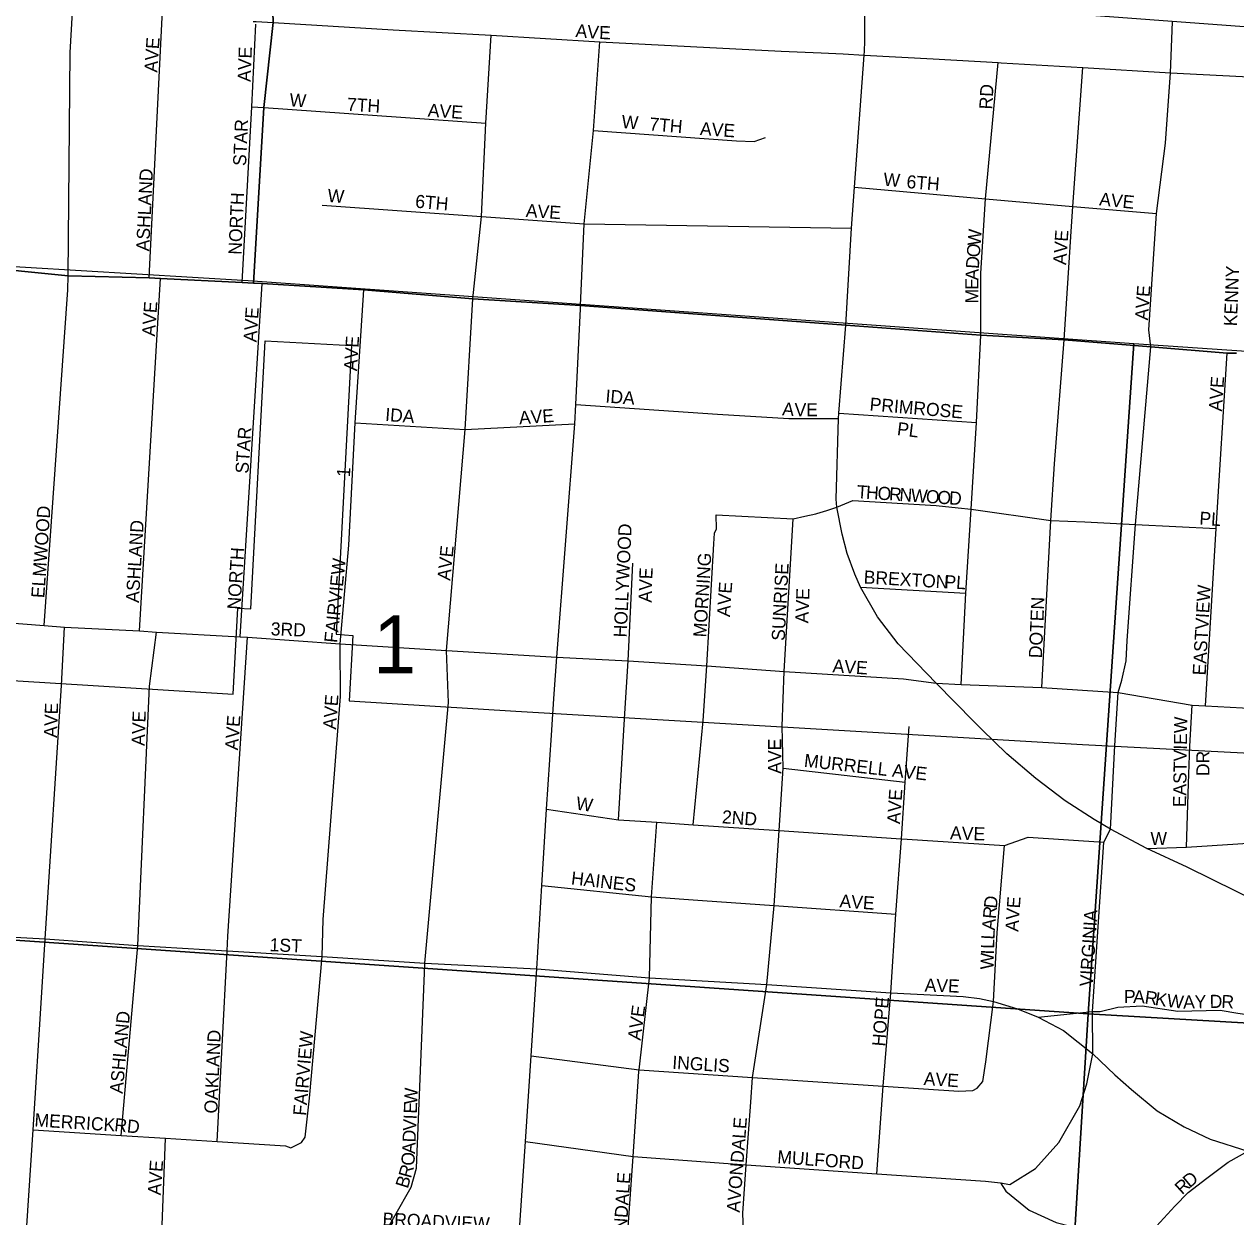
# Model space of a CAD drawing. Extents: x 0 to 34, y -6.2 to 22.
# Drawn here: x 3.949 to 4.825, y 19.243 to 20.105 of the extents above; entities that cross this region are included whole.
import ezdxf

# ---------------------------------------------------------------- set-up
doc = ezdxf.new("R2010")
doc.units = 0
for name, color, linetype in [('GM_X_City_Street', 7, 'Continuous'), ('GM_X_City_Street_Text', 7, 'Continuous'), ('GM_X_Corporation', 7, 'Continuous'), ('GM_X_Section', 7, 'Continuous'), ('GM_X_Section_Text', 7, 'Continuous'), ('GM_X_Township', 7, 'Continuous')]:
    doc.layers.add(name, color=color, linetype=linetype)

msp = doc.modelspace()

# ---------------------------------------------------------------- linework, layer by layer
at = {"layer": 'GM_X_City_Street'}
for points in [[(4.55628, 20.08526), (4.55664, 20.09249), (4.55647, 20.10992), (4.55433, 20.12701), (4.55105, 20.14132), (4.54402, 20.15913), (4.53474, 20.17767), (4.52852, 20.18768), (4.52129, 20.19705), (4.51422, 20.20462), (4.50912, 20.20987), (4.50344, 20.21461), (4.49515, 20.22105), (4.4677, 20.2393), (4.324, 20.3266), (4.19675, 20.40486), (4.17844, 20.41553), (4.15875, 20.42298), (4.14634, 20.42702)], [(3.96346, 19.67023), (3.98059, 19.91279), (3.98086, 19.92294), (3.98244, 20.08445), (3.98408, 20.11355), (3.98655, 20.13903), (3.98852, 20.15761)], [(4.03954, 19.92149), (4.04886, 20.10993), (4.05083, 20.14511)], [(4.10661, 19.91804), (4.11352, 20.04512), (4.11655, 20.10492)], [(4.11465, 20.10685), (4.11664, 20.10677), (4.12905, 20.10601), (4.21566, 20.1007), (4.28652, 20.09692), (4.3651, 20.09199), (4.49614, 20.08542), (4.52499, 20.08415)], [(4.73722, 19.58334), (4.73968, 19.62181), (4.7422, 19.63051), (4.74531, 19.64456), (4.74615, 19.65938), (4.75199, 19.74324), (4.76318, 19.87149), (4.76179, 19.88392), (4.76731, 19.96792), (4.77381, 20.01883), (4.77743, 20.06963), (4.77874, 20.10662)], [(4.25581, 19.61458), (4.25436, 19.65214), (4.26765, 19.81193), (4.27333, 19.90633), (4.27952, 19.9658), (4.28257, 20.03329), (4.28652, 20.09692)], [(4.35108, 19.89896), (4.3512, 19.90135), (4.35383, 19.96053), (4.3605, 20.02804), (4.3651, 20.09199)], [(4.52499, 20.08415), (4.54086, 20.08345), (4.55614, 20.08246), (4.60579, 20.07966), (4.65281, 20.07703), (4.65509, 20.07689)], [(4.54291, 19.88718), (4.54694, 19.95735), (4.54908, 19.98695), (4.55614, 20.08246), (4.55628, 20.08526)], [(4.62625, 19.62756), (4.62953, 19.69349), (4.63348, 19.75432), (4.63726, 19.8168), (4.64043, 19.87993), (4.64046, 19.92487), (4.64374, 19.97859), (4.65281, 20.07703)], [(4.65509, 20.07689), (4.71397, 20.07341), (4.77743, 20.06963), (4.83875, 20.06651), (4.96354, 20.05993), (5.03933, 20.05566), (5.07812, 20.05335), (5.112, 20.05144), (5.16263, 20.04858), (5.1655, 20.04842)], [(4.68444, 19.62526), (4.69085, 19.74612), (4.69366, 19.78699), (4.70068, 19.87655), (4.70558, 19.95491), (4.70681, 19.97314), (4.71397, 20.07341)], [(4.11352, 20.04512), (4.12225, 20.04451), (4.28257, 20.03329)], [(4.3605, 20.02804), (4.46374, 20.02047), (4.47657, 20.01998), (4.48479, 20.02294)], [(4.54908, 19.98695), (4.64374, 19.97859), (4.70681, 19.97314), (4.76731, 19.96792)], [(4.16434, 19.97397), (4.27952, 19.9658), (4.35383, 19.96053), (4.54694, 19.95735)], [(3.82544, 19.93439), (3.84238, 19.93372), (3.91112, 19.92982), (3.98086, 19.92294), (4.03954, 19.92149), (4.04759, 19.92099), (4.10661, 19.91804), (4.11492, 19.91758), (4.12105, 19.91725), (4.19453, 19.91272), (4.27333, 19.90633), (4.3512, 19.90135), (4.54291, 19.88718), (4.64043, 19.87993), (4.70068, 19.87655), (4.76318, 19.87149), (4.81835, 19.86698), (4.82512, 19.86698)], [(4.03249, 19.66631), (4.04759, 19.92099)], [(4.10529, 19.66194), (4.12105, 19.91725)], [(4.17778, 19.61885), (4.17749, 19.65697), (4.18381, 19.72829), (4.18818, 19.81654), (4.19453, 19.91272)], [(4.33218, 19.62079), (4.33394, 19.64732), (4.34699, 19.81583), (4.34773, 19.8299), (4.35108, 19.89896)], [(4.63532, 19.60081), (4.60816, 19.62838), (4.58054, 19.65683), (4.56574, 19.67639), (4.55341, 19.69793), (4.5493, 19.70714), (4.54388, 19.72226), (4.54009, 19.73623), (4.53641, 19.75579), (4.53576, 19.76138), (4.53757, 19.81975), (4.53773, 19.82352), (4.54291, 19.88718)], [(4.80259, 19.61207), (4.8104, 19.74032), (4.81835, 19.86698)], [(4.34773, 19.8299), (4.45011, 19.82303), (4.50173, 19.81975), (4.53757, 19.81975)], [(4.53773, 19.82352), (4.63726, 19.8168)], [(4.18818, 19.81654), (4.26765, 19.81193), (4.34699, 19.81583)], [(4.52179, 19.75109), (4.52908, 19.75317), (4.53641, 19.75579), (4.54782, 19.76057), (4.608, 19.75678), (4.62392, 19.75524)], [(4.44946, 19.73994), (4.44918, 19.75005), (4.50475, 19.74725), (4.51313, 19.74906), (4.52102, 19.75087), (4.52179, 19.75109)], [(4.62392, 19.75524), (4.63348, 19.75432), (4.69085, 19.74612), (4.71547, 19.74506), (4.75199, 19.74324), (4.8104, 19.74032)], [(4.49669, 19.59732), (4.49834, 19.63677), (4.50475, 19.74725)], [(4.43975, 19.6012), (4.44246, 19.64099), (4.44732, 19.72928), (4.44798, 19.73688), (4.44946, 19.73994)], [(4.3832, 19.60646), (4.38549, 19.64461), (4.38902, 19.71524)], [(4.55341, 19.69793), (4.62953, 19.69349)], [(3.87315, 19.67688), (3.89593, 19.67566), (3.91115, 19.67415), (3.96346, 19.67023), (3.97823, 19.66903), (4.03249, 19.66631), (4.0447, 19.66541), (4.10529, 19.66194), (4.11056, 19.66179), (4.17749, 19.65697), (4.25436, 19.65214), (4.33394, 19.64732), (4.38549, 19.64461), (4.44246, 19.64099), (4.49834, 19.63677), (4.58448, 19.63151), (4.60816, 19.62838), (4.62625, 19.62756), (4.68444, 19.62526), (4.73968, 19.62181), (4.79301, 19.61257), (4.80259, 19.61207), (4.83822, 19.61008)], [(3.97612, 19.62671), (3.97823, 19.66903)], [(4.03961, 19.62628), (4.0447, 19.66541)], [(4.08847, 19.29709), (4.09575, 19.43488), (4.09631, 19.44544), (4.11056, 19.66179)], [(3.94946, 19.21059), (3.95555, 19.30564), (3.96165, 19.40086), (3.96439, 19.44362), (3.97612, 19.62671)], [(4.01911, 19.30156), (4.03128, 19.4388), (4.03961, 19.62628)], [(4.14961, 19.29647), (4.15218, 19.30033), (4.15532, 19.32854), (4.16444, 19.43089), (4.16521, 19.45769), (4.17778, 19.61885)], [(4.33019, 19.59098), (4.33119, 19.606), (4.33218, 19.62079)], [(4.23842, 19.41915), (4.23871, 19.42606), (4.25581, 19.61458)], [(4.7913, 19.58302), (4.79301, 19.61257)], [(4.37856, 19.52977), (4.3832, 19.60646)], [(4.43251, 19.52607), (4.43975, 19.6012)], [(4.84276, 19.46924), (4.7895, 19.49555), (4.76023, 19.50886), (4.73393, 19.52301), (4.72225, 19.52991), (4.70138, 19.54339), (4.68, 19.5595), (4.65904, 19.57742), (4.64104, 19.59501), (4.63532, 19.60081)], [(4.47326, 19.21418), (4.46941, 19.21945), (4.46831, 19.24528), (4.47085, 19.28029), (4.47412, 19.32556), (4.47543, 19.34344), (4.48569, 19.41068), (4.49105, 19.46774), (4.49463, 19.52183), (4.49762, 19.56689), (4.49669, 19.59732)], [(4.56518, 19.27379), (4.56986, 19.33714), (4.57534, 19.40453), (4.579, 19.46142), (4.58297, 19.51586), (4.58576, 19.55679), (4.58851, 19.59704)], [(4.3196, 19.42202), (4.32311, 19.48226), (4.32663, 19.53742), (4.33019, 19.59098)], [(4.65446, 19.26736), (4.66132, 19.26593), (4.67978, 19.27756), (4.69662, 19.29639), (4.7118, 19.32301), (4.71706, 19.33883), (4.72124, 19.36058), (4.72102, 19.39113), (4.72916, 19.51363), (4.73393, 19.52301), (4.73722, 19.58334)], [(4.789, 19.51001), (4.7905, 19.55603), (4.7913, 19.58302)], [(4.49762, 19.56689), (4.58576, 19.55679)], [(4.32663, 19.53742), (4.37856, 19.52977), (4.40624, 19.52787), (4.43251, 19.52607), (4.49463, 19.52183), (4.5685, 19.51678), (4.57928, 19.5161), (4.58297, 19.51586), (4.58708, 19.5156)], [(4.3834, 19.2047), (4.38907, 19.28624), (4.39334, 19.34774), (4.39342, 19.34888), (4.40087, 19.41551), (4.40236, 19.47407), (4.40624, 19.52787)], [(4.58708, 19.5156), (4.65743, 19.51112), (4.67458, 19.51708), (4.72916, 19.51363)], [(4.76023, 19.50886), (4.789, 19.51001), (4.84457, 19.51347), (4.89781, 19.50871), (4.8986, 19.50868), (4.95143, 19.50678), (4.95251, 19.50673), (5.0091, 19.5125), (5.06394, 19.50921), (5.09824, 19.50717)], [(4.63765, 19.33557), (4.64175, 19.34056), (4.64386, 19.35465), (4.64961, 19.39837), (4.65215, 19.44826), (4.65743, 19.51112)], [(4.32311, 19.48226), (4.40236, 19.47407), (4.43922, 19.47146), (4.49105, 19.46774), (4.579, 19.46142)], [(3.89813, 19.44715), (3.96439, 19.44362), (4.03128, 19.4388), (4.09575, 19.43488), (4.16444, 19.43089), (4.23871, 19.42606), (4.31959, 19.42191), (4.40087, 19.41551), (4.48569, 19.41068), (4.57534, 19.40453), (4.62764, 19.40189), (4.6395, 19.40057), (4.64961, 19.39837), (4.66675, 19.3931), (4.68169, 19.38695), (4.70015, 19.37728), (4.72124, 19.36058), (4.73706, 19.3452), (4.74925, 19.33466), (4.76782, 19.31927), (4.78716, 19.30784), (4.80606, 19.29878), (4.83339, 19.29008)], [(4.20209, 19.07769), (4.19045, 19.17573), (4.18859, 19.19014), (4.19581, 19.20665), (4.20504, 19.22278), (4.22867, 19.26409), (4.23253, 19.27786), (4.23842, 19.41915)], [(4.29651, 19.07423), (4.29867, 19.10855), (4.30082, 19.14616), (4.30377, 19.18709), (4.31126, 19.29714), (4.31552, 19.35897), (4.31959, 19.42191), (4.3196, 19.42202)], [(4.68169, 19.38695), (4.72102, 19.39113), (4.72655, 19.39103), (4.73942, 19.39423), (4.75687, 19.39521), (4.78274, 19.39135), (4.81333, 19.39214), (4.82616, 19.38983), (4.83619, 19.38852), (4.84737, 19.38901)], [(4.31552, 19.35897), (4.39342, 19.34888), (4.47543, 19.34344), (4.56986, 19.33714), (4.62438, 19.33351), (4.63463, 19.33401), (4.63765, 19.33557)], [(3.95555, 19.30564), (4.01911, 19.30156), (4.05121, 19.29949), (4.08847, 19.29709), (4.13788, 19.29391), (4.14171, 19.29248), (4.14961, 19.29647)], [(4.01663, 19.06068), (4.01664, 19.06076), (4.01763, 19.07013), (4.02183, 19.16876), (4.0231, 19.17944), (4.04062, 19.21066), (4.04828, 19.22414), (4.04856, 19.2316), (4.04875, 19.2367), (4.05121, 19.29949)], [(4.31126, 19.29714), (4.38907, 19.28624), (4.47085, 19.28029), (4.56518, 19.27379), (4.64382, 19.26837), (4.65446, 19.26736), (4.65834, 19.26133), (4.67522, 19.24747), (4.6947, 19.23859), (4.70521, 19.23591), (4.72022, 19.23207), (4.75747, 19.22987), (4.76723, 19.23594), (4.77075, 19.23004), (4.81846, 19.19945), (4.8262, 19.20919), (4.83544, 19.21468), (4.84443, 19.21643), (4.86416, 19.21593), (4.9246, 19.21268), (4.9638, 19.20919), (4.97529, 19.20544), (4.9845, 19.20072)], [(4.72818, 18.92661), (4.73315, 19.05125), (4.73748, 19.15968), (4.74881, 19.19403), (4.76723, 19.23594), (4.78057, 19.25047), (4.79005, 19.26025), (4.80368, 19.27062), (4.8191, 19.28218), (4.83339, 19.29008)]]:
    msp.add_lwpolyline(points, dxfattribs=at)
at = {"layer": 'GM_X_Corporation'}
for points in [[(4.84351, 20.10198), (4.60673, 20.11958), (4.61391, 20.22562), (4.63396, 20.22482), (4.63452, 20.25758), (4.6752, 20.25534), (4.67446, 20.23323), (4.72423, 20.2299), (4.72565, 20.25256), (4.79626, 20.24867), (4.79674, 20.25812), (4.84545, 20.25539)], [(3.63269, 19.11233), (3.65812, 19.45713), (3.65848, 19.46257), (3.6922, 19.94158), (3.74012, 19.93873), (3.82109, 19.93456), (3.79749, 19.70726), (3.87046, 19.70415), (3.87047, 19.63478), (4.10008, 19.62046), (4.10338, 19.68258), (4.11283, 19.68208), (4.12313, 19.87591), (4.18554, 19.87259), (4.17445, 19.66384), (4.18653, 19.663), (4.18399, 19.61568), (4.30426, 19.60822), (4.71375, 19.58418), (5.32348, 19.55244)], [(3.87047, 19.63478), (4.10008, 19.62046), (4.10338, 19.68258), (4.11283, 19.68208), (4.12313, 19.87591), (4.18554, 19.87259), (4.17445, 19.66384), (4.18653, 19.663), (4.18399, 19.61568), (4.30426, 19.60822), (4.71375, 19.58418), (5.32348, 19.55244)]]:
    msp.add_lwpolyline(points, dxfattribs=at)
at = {"layer": 'GM_X_Section'}
for points in [[(3.70844, 19.94367), (4.11096, 19.9196), (4.75087, 19.87398), (4.71794, 19.38931), (3.68273, 19.46047)], [(5.77359, 19.80442), (5.74527, 19.32804), (5.23224, 19.35957), (4.71794, 19.38931), (4.75087, 19.87398)], [(4.71794, 19.38931), (5.23224, 19.35957), (5.17024, 18.38679), (4.97661, 18.40016), (4.96149, 18.40555), (4.94372, 18.41097), (4.915, 18.42251), (4.89649, 18.43134), (4.89237, 18.43704), (4.88678, 18.45299), (4.88341, 18.45907), (4.87171, 18.46596), (4.85851, 18.47551), (4.84495, 18.48809), (4.8265, 18.50677), (4.80881, 18.52469), (4.78244, 18.54682), (4.76999, 18.55599), (4.74885, 18.56786), (4.72015, 18.58167), (4.68881, 18.59815), (4.66994, 18.61077)]]:
    msp.add_lwpolyline(points, close=True, dxfattribs=at)
msp.add_lwpolyline([(3.63666, 18.56374), (3.68273, 19.46047), (4.71794, 19.38931), (4.66994, 18.61077)], dxfattribs=at)
at = {"layer": 'GM_X_Township'}
for points in [[(3.91113, 19.92982), (3.98086, 19.92295), (4.03954, 19.92149), (4.04759, 19.92099), (4.10661, 19.91804), (4.11492, 19.91758), (4.12225, 20.04451), (4.12905, 20.10601), (4.1276, 20.15181), (4.12848, 20.18711), (4.13308, 20.26403), (4.13842, 20.31918), (4.14285, 20.42815), (4.15632, 20.59561), (4.15959, 20.68147), (4.14699, 20.68115), (4.14165, 20.68104), (4.14048, 20.71359)], [(4.14048, 20.71359), (4.14165, 20.68104), (4.14699, 20.68115), (4.15959, 20.68147), (4.15632, 20.59561), (4.14285, 20.42815), (4.13842, 20.31918), (4.13308, 20.26403), (4.12848, 20.18711), (4.1276, 20.15181), (4.12905, 20.10601), (4.12225, 20.04451), (4.11492, 19.91758), (4.12106, 19.91725), (4.19453, 19.91272), (4.27333, 19.90633), (4.35119, 19.90135), (4.54291, 19.88718), (4.64043, 19.87993), (4.70068, 19.87656), (4.76318, 19.87149), (4.81836, 19.86698), (4.82511, 19.86698)], [(4.82511, 19.86698), (4.81836, 19.86698), (4.76318, 19.87149), (4.70068, 19.87656), (4.64043, 19.87993), (4.54291, 19.88718), (4.35119, 19.90135), (4.27333, 19.90633), (4.19453, 19.91272), (4.12106, 19.91725), (4.11492, 19.91758), (4.10661, 19.91804), (4.04759, 19.92099), (4.03954, 19.92149), (3.98086, 19.92295), (3.91113, 19.92982)]]:
    msp.add_lwpolyline(points, dxfattribs=at)

# ---------------------------------------------------------------- texts
at = {"layer": 'GM_X_City_Street_Text'}
for s, height, rotation, p in [('A', 0.00947, 355.12019, (4.34725, 20.09555)), ('V', 0.00947, 355.12019, (4.35556, 20.09484)), ('E', 0.00947, 358.36168, (4.36445, 20.0941)), ('AVE', 0.00947, 86.05688, (4.0453, 20.06974)), ('AVE', 0.00947, 88.01857, (4.1128, 20.06301)), ('RD', 0.00947, 86.98841, (4.64863, 20.04304)), ('W', 0.00947, 355.60387, (4.14055, 20.04555)), ('7TH', 0.00947, 356.73129, (4.18218, 20.04222)), ('AVE', 0.00947, 356.05688, (4.24053, 20.03806)), ('W', 0.00947, 355.60387, (4.38054, 20.02972)), ('STAR', 0.00947, 87.51167, (4.10946, 20.00219)), ('7TH', 0.00947, 355.09737, (4.40056, 20.02805)), ('AVE', 0.00947, 356.05688, (4.4372, 20.02472)), ('ASHLAND', 0.00947, 87.39878, (4.03946, 19.94053)), ('W', 0.00947, 355.60387, (4.56971, 19.98805)), ('6TH', 0.00947, 355.42886, (4.58638, 19.98639)), ('W', 0.00947, 355.60387, (4.16805, 19.97639)), ('NORTH', 0.00947, 87.61083, (4.10613, 19.93802)), ('6TH', 0.00947, 355.10357, (4.2314, 19.97222)), ('AVE', 0.00947, 354.09695, (4.72559, 19.97388)), ('AVE', 0.00947, 356.0574, (4.31137, 19.96556)), ('W', 0.00947, 85.59097, (4.64014, 19.94436)), ('AVE', 0.00947, 86.04937, (4.70196, 19.93057)), ('O', 0.00947, 85.60296, (4.6395, 19.93606)), ('D', 0.00947, 85.75552, (4.63889, 19.92775)), ('A', 0.00947, 88.2729, (4.63864, 19.91953)), ('KENNY', 0.00947, 87.66414, (4.82533, 19.88635)), ('E', 0.00947, 89.93222, (4.63864, 19.91294)), ('AVE', 0.00947, 86.05688, (4.76113, 19.89057)), ('M', 0.00947, 89.94535, (4.63863, 19.90294)), ('AVE', 0.00947, 86.05688, (4.04363, 19.8789)), ('AVE', 0.00947, 86.05739, (4.11697, 19.87473)), ('AVE', 0.00947, 86.05688, (4.18947, 19.8539)), ('AVE', 0.00947, 86.05688, (4.81447, 19.82474)), ('IDA', 0.00947, 355.42017, (4.36889, 19.83139)), ('A', 0.00947, 355.20731, (4.49664, 19.82219)), ('V', 0.00947, 359.53113, (4.50572, 19.82146)), ('E', 0.00947, 359.99563, (4.51414, 19.82139)), ('PRIMROSE', 0.00947, 355.02985, (4.55973, 19.82556)), ('IDA', 0.00947, 355.42816, (4.20972, 19.81806)), ('AVE', 0.00947, 3.94312, (4.30695, 19.81556)), ('STAR', 0.00947, 86.26602, (4.11113, 19.77973)), ('PL', 0.00947, 352.87835, (4.57947, 19.80789)), ('1', 0.00947, 86.63504, (4.18446, 19.77722)), ('T', 0.00947, 356.11685, (4.55053, 19.76222)), ('H', 0.00947, 356.12776, (4.55718, 19.76177)), ('O', 0.00947, 356.12776, (4.5655, 19.76121)), ('R', 0.00947, 356.11162, (4.57381, 19.76065)), ('N', 0.00947, 356.13067, (4.5813, 19.76014)), ('W', 0.00947, 356.11323, (4.58961, 19.75958)), ('O', 0.00947, 356.13067, (4.60042, 19.75884)), ('O', 0.00947, 356.10595, (4.60873, 19.75828)), ('D', 0.00947, 356.87403, (4.61718, 19.75771)), ('ELMWOOD', 0.00947, 86.08379, (3.96363, 19.68974)), ('PL', 0.00947, 356.18786, (4.79803, 19.74305)), ('ASHLAND', 0.00947, 86.53356, (4.03197, 19.68639)), ('HOLLYWOOD', 0.00947, 87.45416, (4.38446, 19.66136)), ('NORTH', 0.00947, 86.4211, (4.1053, 19.68139)), ('AVE', 0.00947, 84.08948, (4.25697, 19.7023)), ('FAIRVIEW', 0.00947, 84.20724, (4.1753, 19.65729)), ('MORNING', 0.00947, 86.53026, (4.44196, 19.66139)), ('SUNRISE', 0.00947, 87.03705, (4.49863, 19.65887)), ('AVE', 0.00947, 88.02609, (4.40241, 19.68661)), ('BREXTON', 0.00947, 356.53357, (4.55552, 19.70056)), ('PL', 0.00947, 356.41176, (4.61385, 19.69722)), ('AVE', 0.00947, 86.04989, (4.45905, 19.67611)), ('EASTVIEW', 0.00947, 86.7772, (4.8028, 19.63388)), ('AVE', 0.00947, 88.02635, (4.51574, 19.67161)), ('DOTEN', 0.00947, 87.56008, (4.68446, 19.64635)), ('3RD', 0.00947, 357.78998, (4.12715, 19.66306)), ('AVE', 0.00947, 356.05688, (4.53303, 19.63639)), ('AVE', 0.00947, 86.05688, (4.17447, 19.59474)), ('AVE', 0.00947, 88.02609, (3.9728, 19.58884)), ('AVE', 0.00947, 88.02609, (4.03613, 19.58301)), ('AVE', 0.00947, 86.05739, (4.10363, 19.57974)), ('EASTVIEW', 0.00947, 89.19471, (4.78863, 19.53874)), ('AVE', 0.00947, 90, (4.49613, 19.56295)), ('MURRELL AVE', 0.0094697, 353.59691, (4.51227, 19.56805)), ('DR', 0.00947, 90, (4.80557, 19.56128)), ('AVE', 0.00947, 86.05688, (4.58197, 19.5264)), ('W', 0.00947, 351.25889, (4.34735, 19.53721)), ('2ND', 0.00947, 355.76599, (4.45304, 19.52722)), ('AVE', 0.00947, 358.02636, (4.61797, 19.51556)), ('W', 0.00947, 0.00001, (4.76291, 19.51139)), ('HAINES', 0.00947, 353.28942, (4.34395, 19.48305)), ('AVE', 0.00947, 356.04938, (4.53803, 19.46639)), ('D', 0.00947, 84.64317, (4.65191, 19.46526)), ('AVE', 0.00947, 86.04937, (4.66738, 19.44861)), ('R', 0.00947, 84.62528, (4.65121, 19.45779)), ('VIRGINIA', 0.00947, 86.36902, (4.72113, 19.40889)), ('A', 0.00947, 85.00942, (4.65048, 19.44951)), ('1ST', 0.00947, 357.5121, (4.12632, 19.43473)), ('L', 0.00947, 88.15989, (4.64994, 19.43632)), ('L', 0.00947, 87.07481, (4.65015, 19.44294)), ('I', 0.00947, 88.16366, (4.64981, 19.43216)), ('W', 0.00947, 88.18382, (4.64946, 19.42133)), ('AVE', 0.00947, 358.0261, (4.59964, 19.40556)), ('HOPE', 0.00947, 85.23937, (4.57114, 19.36559)), ('P', 0.00947, 359.78142, (4.74373, 19.39723)), ('A', 0.00947, 357.68231, (4.75031, 19.39721)), ('R', 0.00947, 351.98325, (4.75838, 19.39689)), ('K', 0.00947, 351.02283, (4.76577, 19.39585)), ('W', 0.00947, 353.4796, (4.77444, 19.39449)), ('A', 0.00947, 1.27695, (4.78661, 19.3932)), ('Y', 0.00947, 1.49111, (4.79498, 19.39338)), ('D', 0.00947, 0.56835, (4.80577, 19.39366)), ('R', 0.00947, 356.62213, (4.81393, 19.39375)), ('ASHLAND', 0.00947, 84.80496, (4.0203, 19.33144)), ('AVE', 0.00947, 82.14336, (4.39448, 19.36986)), ('OAKLAND', 0.00947, 87.50865, (4.08863, 19.31719)), ('FAIRVIEW', 0.00947, 85.03216, (4.15279, 19.3155)), ('INGLIS', 0.00947, 356.27046, (4.41719, 19.34972)), ('AVE', 0.00947, 356.05688, (4.59887, 19.33806)), ('W', 0.00947, 87.57698, (4.23306, 19.32379)), ('E', 0.00947, 87.55447, (4.23278, 19.31712)), ('MERRICK', 0.00947, 356.36902, (3.95636, 19.30806)), ('RD', 0.00947, 353.98321, (4.01393, 19.30472)), ('V', 0.00947, 87.5731, (4.23225, 19.30464)), ('I', 0.00947, 87.55293, (4.23261, 19.31296)), ('AVONDALE', 0.00947, 85.60365, (4.46614, 19.24558)), ('D', 0.00947, 87.59494, (4.2319, 19.29632)), ('A', 0.00947, 87.60586, (4.23156, 19.28799)), ('O', 0.00947, 85.51057, (4.23088, 19.27931)), ('MULFORD', 0.00947, 355.7938, (4.49304, 19.2814)), ('AVE', 0.00947, 86.04937, (4.0478, 19.25807)), ('R', 0.00947, 74.45149, (4.22853, 19.27012)), ('B', 0.00947, 72.76334, (4.22622, 19.26266)), ('GLENDALE', 0.00947, 86.13377, (4.3828, 19.20723)), ('R', 0.00947, 42.54327, (4.78582, 19.25822)), ('D', 0.00947, 39.7216, (4.79126, 19.26321)), ('BROADVIEW', 0.00947, 357.30716, (4.20788, 19.2364))]:
    msp.add_text(s, height=height, rotation=rotation, dxfattribs=at).set_placement(p)
at = {"layer": 'GM_X_Section_Text'}
msp.add_text('1', height=0.04186, rotation=0.00001, dxfattribs=at).set_placement((4.20124, 19.63551))

doc.saveas('drawing.dxf')
